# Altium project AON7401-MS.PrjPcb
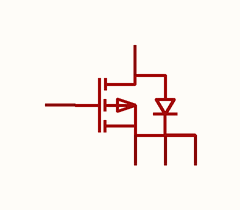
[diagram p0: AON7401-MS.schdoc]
1 sheet, 1 parts. Net scope: global (net labels, ports and power ports of the same name join across sheets).

## Sheet AON7401-MS.schdoc
size 127 x 101 mm

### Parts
Q?  aon7401-ms  [POWERDI3333-8_DMN7022LFGQ-7]  (value not drawn)

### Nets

Not connected (* = marked no-connect by the designer): Q? 1(S) 2(S) 3(S) 4(G) 5(D)

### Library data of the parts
Q? = aon7401-ms: 数量:1个P沟道;漏源电压(Vdss):30V;连续漏极电流(Id):50A;导通电阻(RDS(on)):13mΩ@10V;耗散功率(Pd):37W;阈值电压(Vgs(th)):-;; Manufacturer: MSKSEMI(美森科); AddInBom: yes; ModelId: 296e462280334ba794f41fc0f4558c2c; ModelTransform: 130.708,130.708,0,0,0,0,0,18.625,0; Number: 1个P沟道; Drain to Source Voltage: 30V; Current - Continuous Drain(Id): 50A; Pd - Power Dissipation: 37W; Gate Charge(Qg): 22nC@4.5V; Input Capacitance(Ciss): 2.215nF; Reverse Transfer Capacitance (Crss@Vds): 237pF; Type: P沟道; Output Capacitance(Coss): 310pF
